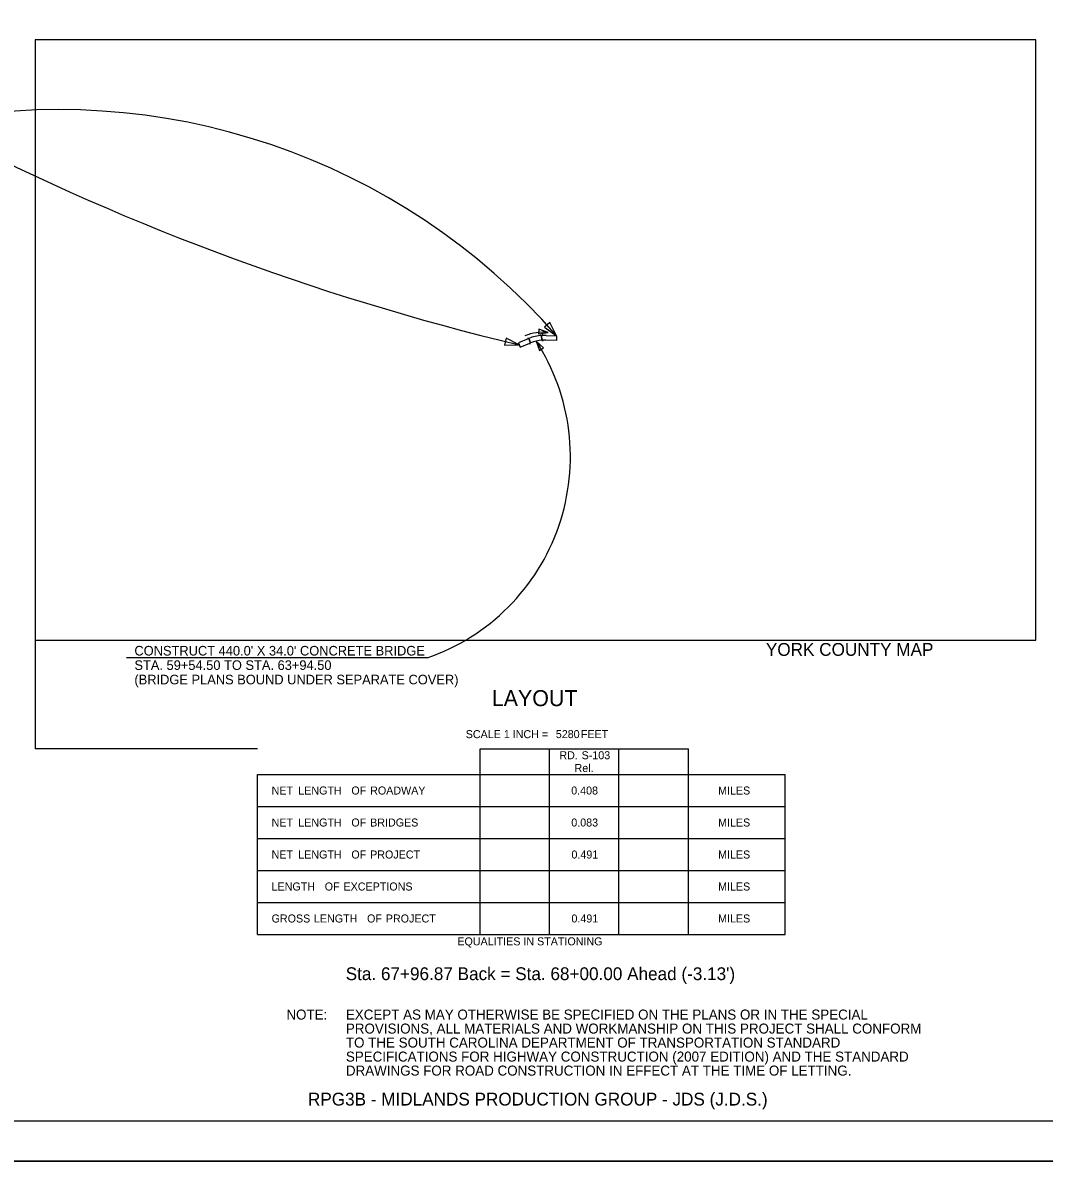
# Model space of a CAD drawing. Extents: x -796 to 2793, y -4650 to 4425.
# Drawn here: x 1596 to 2234, y 1000 to 1711 of the extents above; entities that cross this region are included whole.
import ezdxf

# ---------------------------------------------------------------- set-up
doc = ezdxf.new("R2010")
doc.units = 0
for name, color, linetype in [('RD_EX_Road', 7, 'Continuous'), ('RD_HC_CL', 7, 'Continuous'), ('RD_HC_Data', 7, 'Continuous'), ('RD_HC_Data_Tic', 7, 'Continuous'), ('RD_SHT_Bndy', 7, 'Continuous'), ('RD_Sketch7', 7, 'Continuous'), ('RD_Sketch8', 7, 'Continuous')]:
    doc.layers.add(name, color=color, linetype=linetype)

msp = doc.modelspace()

# ---------------------------------------------------------------- linework, layer by layer
at = {"layer": 'RD_EX_Road'}
msp.add_lwpolyline([(1603.73, 1325.6), (2228.73, 1325.6), (2228.73, 1700.6), (1603.73, 1700.6)], close=True, dxfattribs=at)
at = {"layer": 'RD_HC_CL'}
msp.add_lwpolyline([(984.13, 2100), (2780.13, 2100), (2780.13, 1000), (984.13, 1000)], close=True, dxfattribs=at)
at = {"layer": 'RD_HC_Data'}
for p, q in [((1603.73, 1325.6), (1603.73, 1257.68)), ((1742.67, 1257.68), (1603.73, 1257.68)), ((1881.61, 1257.68), (2011.77, 1257.68)), ((1881.61, 1141.65), (1881.61, 1257.68)), ((1925, 1141.65), (1925, 1257.68)), ((1968.38, 1141.65), (1968.38, 1257.68)), ((2011.77, 1141.65), (2011.77, 1257.68)), ((1742.67, 1241.59), (2072.22, 1241.59)), ((1742.67, 1141.65), (1742.67, 1241.59)), ((2072.22, 1141.65), (2072.22, 1241.59)), ((1742.67, 1221.6), (2072.22, 1221.6)), ((1742.67, 1201.62), (2072.22, 1201.62)), ((1742.67, 1181.63), (2072.22, 1181.63)), ((1742.67, 1161.64), (2072.22, 1161.64)), ((1742.67, 1141.65), (2072.22, 1141.65)), ((2760, 1000), (1000, 1000)), ((1000, 1000), (2759.98, 1000))]:
    msp.add_line(p, q, dxfattribs=at)
msp.add_lwpolyline([(1079.63, 2075.05), (2755.13, 2075.05), (2755.13, 1025), (1079.63, 1025)], close=True, dxfattribs=at)
at = {"layer": 'RD_SHT_Bndy'}
for p, q in [((1925.21, 1523.92), (1921.82, 1520.96)), ((1929.44, 1515.66), (1925.21, 1523.92)), ((1918.41, 1519.86), (1918.06, 1516.88)), ((1918.06, 1516.88), (1924.19, 1517.67)), ((1924.19, 1517.67), (1918.41, 1519.86)), ((1921.82, 1520.96), (1929.44, 1515.66)), ((1897.92, 1514.22), (1896.87, 1509.85)), ((1896.87, 1509.85), (1906.15, 1509.94)), ((1906.15, 1509.94), (1897.92, 1514.22)), ((1916.71, 1512.35), (1918.71, 1506.5)), ((1921.23, 1508.13), (1916.71, 1512.35)), ((1918.71, 1506.5), (1921.23, 1508.13)), ((1848.62, 1314.42), (1660.77, 1314.42)), ((1742.67, 1257.68), (1742.67, 1257.68))]:
    msp.add_line(p, q, dxfattribs=at)
for centre, radius, start, end in [((1618.5, 1244.15), 412.8, 41.12808, 101.44517), ((2277.64, 3060.42), 1594.36, 242.30321, 256.52616), ((1920.78, 1488.36), 29.52, 83.35386, 112.02244), ((1805.06, 1440.08), 133, 289.11885, 32.91618)]:
    msp.add_arc(centre, radius, start, end, dxfattribs=at)
at = {"layer": 'RD_Sketch7'}
for p, q in [((1920.75, 1516.62), (1920.09, 1515.87)), ((1920.09, 1515.87), (1920.29, 1512.87)), ((1911.23, 1514.47), (1912.14, 1514.07)), ((1912.14, 1514.07), (1913.25, 1511.28)), ((1912.85, 1510.37), (1913.25, 1511.28)), ((1921.05, 1512.22), (1920.29, 1512.87))]:
    msp.add_line(p, q, dxfattribs=at)
for radius in [26.5, 23.5]:
    msp.add_arc((1921.88, 1489.43), radius, 93.88226, 111.56824, dxfattribs=at)
at = {"layer": 'RD_Sketch8'}
for p, q in [((1920.29, 1512.87), (1920.09, 1515.87)), ((1913.25, 1511.28), (1912.14, 1514.07))]:
    msp.add_line(p, q, dxfattribs=at)
for points in [[(1922.88, 1515.91), (1929.44, 1515.66), (1929.32, 1512.67), (1922.76, 1512.91)], [(1911.64, 1513.87), (1905.57, 1511.32), (1906.73, 1508.56), (1912.8, 1511.1)]]:
    msp.add_lwpolyline(points, dxfattribs=at)
for radius, start, end in [(26.5, 87.85793, 93.88226), (26.5, 111.56824, 112.74093), (23.5, 111.56824, 112.74093), (23.5, 87.85793, 93.88226)]:
    msp.add_arc((1921.88, 1489.43), radius, start, end, dxfattribs=at)

# ---------------------------------------------------------------- texts
at = {"layer": 'RD_HC_Data_Tic'}
for s, height, p in [('LAYOUT', 10, (1888.97, 1284.3)), ('SCALE 1 INCH =           FEET', 5, (1872.7, 1264.3)), ('RD.', 5, (1931.18, 1251.13)), (' S-103', 5, (1943.22, 1251.13)), ('Rel.', 5, (1940.67, 1243.13)), ('NET', 5, (1751.45, 1229.1)), (' LENGTH', 5, (1766.24, 1229.1)), (' OF', 5, (1799.41, 1229.1)), (' ROADWAY', 5, (1811.14, 1229.1)), ('0.408', 5, (1938.58, 1229.1)), ('MILES', 5, (2030.31, 1229.1)), ('NET', 5, (1751.45, 1209.11)), (' LENGTH', 5, (1766.24, 1209.11)), (' OF', 5, (1799.41, 1209.11)), (' BRIDGES', 5, (1811.14, 1209.11)), ('0.083', 5, (1938.63, 1209.11)), ('MILES', 5, (2030.31, 1209.11)), ('NET', 5, (1751.45, 1189.12)), (' LENGTH', 5, (1766.24, 1189.12)), (' OF', 5, (1799.41, 1189.12)), (' PROJECT', 5, (1811.14, 1189.12)), ('0.491', 5, (1938.73, 1189.12)), ('MILES', 5, (2030.31, 1189.12)), ('LENGTH', 5, (1751.45, 1169.13)), (' OF', 5, (1782.78, 1169.13)), (' EXCEPTIONS', 5, (1794.51, 1169.13)), ('MILES', 5, (2030.31, 1169.13)), ('GROSS', 5, (1751.45, 1149.15)), (' LENGTH', 5, (1776.04, 1149.15)), (' OF', 5, (1809.21, 1149.15)), (' PROJECT', 5, (1820.94, 1149.15)), ('0.491', 5, (1938.73, 1149.15)), ('MILES', 5, (2030.31, 1149.15)), ('EQUALITIES IN STATIONING', 5.0001, (1867.47, 1134.85)), ('NOTE:     EXCEPT AS MAY OTHERWISE BE SPECIFIED ON THE PLANS OR IN THE SPECIAL ', 6.2499, (1760.7, 1088.5)), ('                PROVISIONS, ALL MATERIALS AND WORKMANSHIP ON THIS PROJECT SHALL CONFORM ', 6.2499, (1760.7, 1079.75)), ('                TO THE SOUTH CAROLINA DEPARTMENT OF TRANSPORTATION STANDARD ', 6.2499, (1760.7, 1071)), ('                SPECIFICATIONS FOR HIGHWAY CONSTRUCTION (2007 EDITION) AND THE STANDARD', 6.2499, (1760.7, 1062.25)), ('                DRAWINGS FOR ROAD CONSTRUCTION IN EFFECT AT THE TIME OF LETTING.', 6.2499, (1760.7, 1053.5))]:
    msp.add_text(s, height=height, dxfattribs=at).set_placement(p)
at = {"layer": 'RD_SHT_Bndy'}
for s, height, p in [('YORK COUNTY MAP', 8, (2060.18, 1315.73)), ("CONSTRUCT 440.0' X 34.0' CONCRETE BRIDGE", 6, (1665.77, 1315.92)), ('STA. 59+54.50 TO STA. 63+94.50', 6, (1665.77, 1306.92)), ('(BRIDGE PLANS BOUND UNDER SEPARATE COVER)', 6, (1665.77, 1297.92)), ('5280', 5, (1928.96, 1264.34)), ("Sta. 67+96.87 Back = Sta. 68+00.00 Ahead (-3.13')", 8, (1797.74, 1113.14)), ('RPG3B - MIDLANDS PRODUCTION GROUP - JDS (J.D.S.)', 8, (1774.18, 1034.8))]:
    msp.add_text(s, height=height, dxfattribs=at).set_placement(p)

doc.saveas('drawing.dxf')
